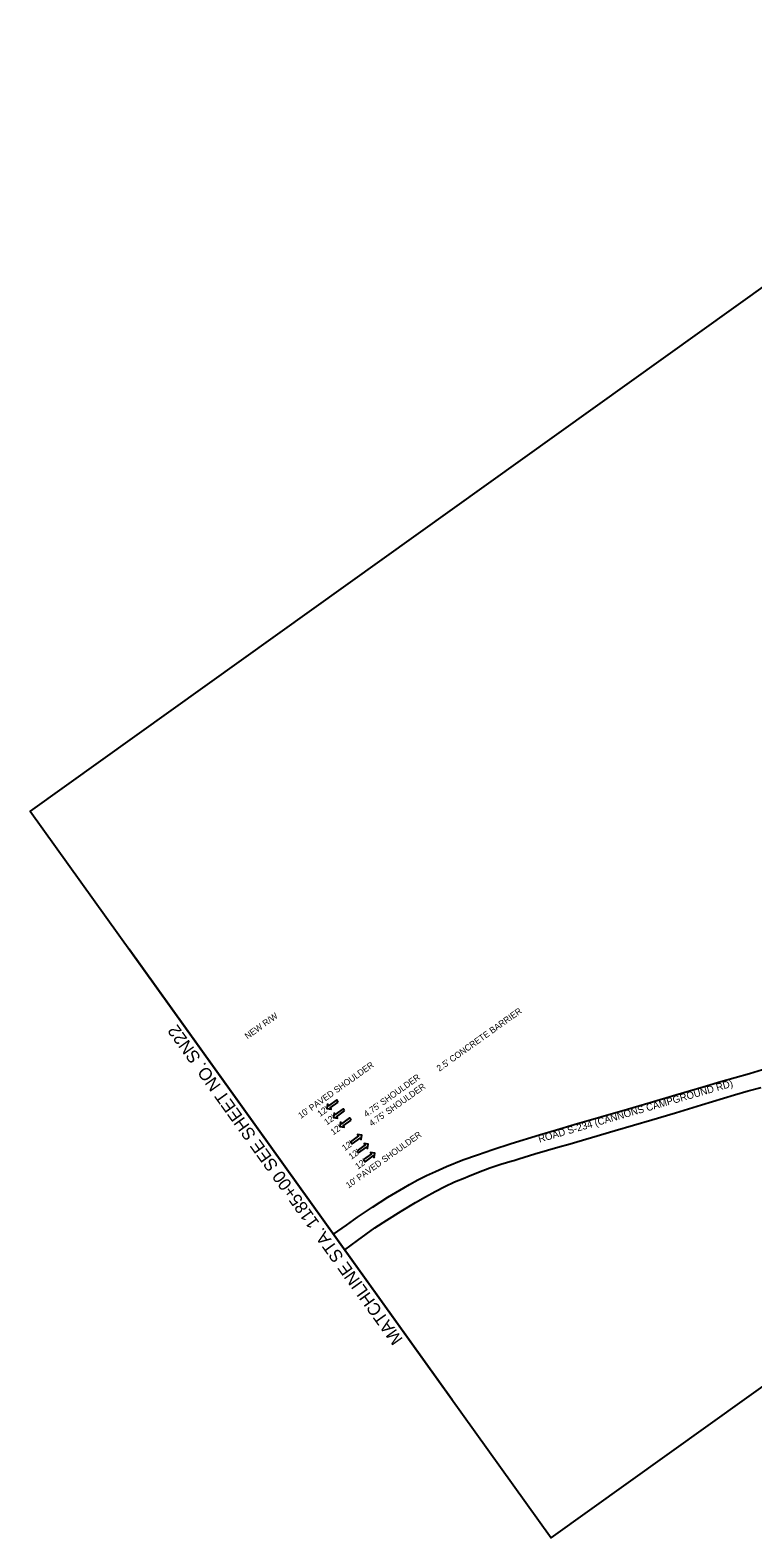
# Model space of a CAD drawing. Extents: x 1768493 to 1770234, y 1176196 to 1177920.
# Drawn here: x 1768493 to 1769301, y 1176196 to 1177883 of the extents above; entities that cross this region are included whole.
import ezdxf

# ---------------------------------------------------------------- set-up
doc = ezdxf.new("R2010")
doc.units = 0
for name, color, linetype in [('RD_DTM_BkLn2', 7, 'Continuous'), ('RD_EX_Bldg', 7, 'Continuous'), ('RD_EX_Conc', 7, 'Continuous'), ('RD_EX_DR_Inlet_txCode', 7, 'Continuous'), ('RD_EX_Fence_Other', 7, 'Continuous'), ('RD_EX_H2O', 7, 'Continuous'), ('RD_SMD_Locator', 7, 'Continuous')]:
    doc.layers.add(name, color=color, linetype=linetype)

# ---------------------------------------------------------------- blocks, each defined once
blk = doc.blocks.new('SARRW2')
at = {"layer": 'RD_EX_Bldg'}
blk.add_lwpolyline([(-12, 1.2), (-12, -1.2), (-2.8, -1.2), (-2.8, -2.8), (0, 0), (-2.8, 2.8), (-2.8, 1.2)], close=True, dxfattribs=at)

msp = doc.modelspace()

# ---------------------------------------------------------------- linework, layer by layer
at = {"layer": 'RD_DTM_BkLn2'}
msp.add_lwpolyline([(1768964.7, 1176350.8), (1768603.7, 1176854.9)], dxfattribs=at)
at = {"layer": 'RD_EX_DR_Inlet_txCode'}
msp.add_lwpolyline([(1769642.1, 1176602.3), (1769580.9, 1176687.6), (1770233.7, 1177155.2), (1769712.5, 1177882.8), (1769712.5, 1177882.8), (1768493.1, 1177009.3), (1769075.4, 1176196.4)], close=True, dxfattribs=at)
at = {"layer": 'RD_SMD_Locator'}
for points in [[(1768832, 1176536.1), (1768846.4, 1176546.1), (1768858.9, 1176555), (1768875.6, 1176566.3), (1768892.6, 1176577.3), (1768901.6, 1176582.6), (1768910.5, 1176587.8), (1768916.9, 1176591.6), (1768926.4, 1176596.9), (1768936, 1176601.8), (1768945.9, 1176606.3), (1768958.2, 1176611.6), (1768976.7, 1176619.3), (1768993, 1176624.8), (1769010.1, 1176630.7), (1769030.5, 1176637.3), (1769062.1, 1176647.2), (1769081.1, 1176652.7), (1769101.1, 1176658.6), (1769130.8, 1176667.3), (1769160.4, 1176675.7), (1769185.8, 1176683.2), (1769214.4, 1176691.8), (1769245.1, 1176701), (1769265, 1176706.8), (1769296.9, 1176715.8), (1769321.1, 1176723.1)], [(1768844.6, 1176518.6), (1768858.7, 1176529), (1768878.1, 1176543.2), (1768891.5, 1176551.7), (1768907.6, 1176561.8), (1768923.8, 1176571.6), (1768934.8, 1176577.9), (1768945.5, 1176583.8), (1768956.4, 1176589.2), (1768967.4, 1176594.4), (1768978.7, 1176599.2), (1768982, 1176600.5), (1768994.2, 1176605.5), (1769006.6, 1176610.1), (1769019.1, 1176614.3), (1769031.7, 1176618.1), (1769033.5, 1176618.6), (1769039.3, 1176620.4), (1769057.2, 1176626), (1769085.2, 1176634), (1769093.8, 1176636.5), (1769146.8, 1176651.9), (1769187.8, 1176663.8), (1769214.2, 1176671.7), (1769243.1, 1176680.7), (1769280, 1176691.9), (1769295.6, 1176696.2), (1769309.9, 1176700.2)]]:
    msp.add_lwpolyline(points, dxfattribs=at)

# ---------------------------------------------------------------- block references
at = {"layer": 'RD_EX_Bldg', "xscale": 1.1999999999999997}
for p, yscale, rotation in [((1768824.7, 1176676.6), 1.2000000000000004, -144.38650217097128), ((1768831.9, 1176666.6), 1.2000000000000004, -144.38650217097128), ((1768839.2, 1176656.5), 1.2000000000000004, -144.38650217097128), ((1768863.6, 1176646.7), 1.2, 35.61349782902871), ((1768870.9, 1176636.6), 1.2, 35.61349782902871), ((1768878.1, 1176626.6), 1.2, 35.61349782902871)]:
    msp.add_blockref('SARRW2', p, dxfattribs=dict(at, yscale=yscale, rotation=rotation))

# ---------------------------------------------------------------- texts
at = {"layer": 'RD_DTM_BkLn2'}
msp.add_text('MATCHLINE STA. 1185+00 SEE SHEET NO. SN22', height=14, rotation=125.6135, dxfattribs=at).set_placement((1768910.1, 1176418.5))
at = {"layer": 'RD_EX_Conc'}
msp.add_text('ROAD S-234 (CANNONS CAMPGROUND RD) ', height=8, rotation=16.1818, dxfattribs=at).set_placement((1769062.2, 1176638.4))
at = {"layer": 'RD_EX_Fence_Other'}
msp.add_text('NEW R/W', height=7, rotation=35.6135, dxfattribs=at).set_placement((1768735.9, 1176753.8))
at = {"layer": 'RD_EX_H2O'}
for s, p in [("2.5' CONCRETE BARRIER", (1768950.4, 1176717.7)), ("10' PAVED SHOULDER", (1768795.6, 1176664.9)), ("4.75' SHOULDER", (1768868.9, 1176666.6)), ("4.75' SHOULDER", (1768874.9, 1176656.3)), ("12'", (1768817.1, 1176667)), ("12'", (1768824.6, 1176657.6)), ("12'", (1768831.8, 1176646.5)), ("10' PAVED SHOULDER", (1768848.9, 1176587)), ("12'", (1768844.6, 1176628.7)), ("12'", (1768852.1, 1176619.2)), ("12'", (1768859.3, 1176608.1))]:
    msp.add_text(s, height=7, rotation=35.6135, dxfattribs=at).set_placement(p)

doc.saveas('drawing.dxf')
